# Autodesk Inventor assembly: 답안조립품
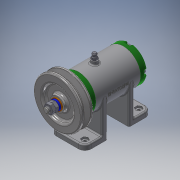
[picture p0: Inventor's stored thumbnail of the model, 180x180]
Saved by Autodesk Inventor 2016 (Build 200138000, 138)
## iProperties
Created: 2017-02
Part Number: 답안조립품
Material: 일반
Document SubType Name: Assembly
Designer: USER
Author: USER
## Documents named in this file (16)
- C:\Users\USER\Desktop\470207V1028\답안조립품.iam
- C:\Users\USER\Desktop\470207V1028\V벨트풀리.ipt
- C:\Users\USER\Desktop\470207V1028\너트 M 8.ipt
- C:\Users\USER\Desktop\470207V1028\니플 M 6 x 0.75.ipt
- C:\Users\USER\Desktop\470207V1028\뒤커버.ipt
- C:\Users\USER\Desktop\470207V1028\베어링 15 x 32 x 9.ipt
- C:\Users\USER\Desktop\470207V1028\본체.ipt
- C:\Users\USER\Desktop\470207V1028\볼트 M 6 x 8.ipt
- C:\Users\USER\Desktop\470207V1028\볼트 M4 x 12.ipt
- C:\Users\USER\Desktop\470207V1028\스프링와셔 8.ipt
- C:\Users\USER\Desktop\470207V1028\앞커버.ipt
- C:\Users\USER\Desktop\470207V1028\오일 실 15 25 7.ipt
- C:\Users\USER\Desktop\470207V1028\와셔 6x11.5.ipt
- C:\Users\USER\Desktop\470207V1028\와셔 8x17.ipt
- C:\Users\USER\Desktop\470207V1028\축.ipt
- C:\Users\USER\Desktop\470207V1028\키 3 x 3 x 12.ipt
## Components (11 placed, 3 different names)
1. V벨트풀리:1
2. KS B 2023 6002 - 15 x 32 x 9:1
3. KS B 2023 6002 - 15 x 32 x 9:2
4. ISO 4762 M4 x 12:2
5. ISO 4762 M4 x 12:3
6. ISO 4762 M4 x 12:4
7. ISO 4762 M4 x 12:5
8. ISO 4762 M4 x 12:1
9. ISO 4762 M4 x 12:6
10. ISO 4762 M4 x 12:7
11. ISO 4762 M4 x 12:8
